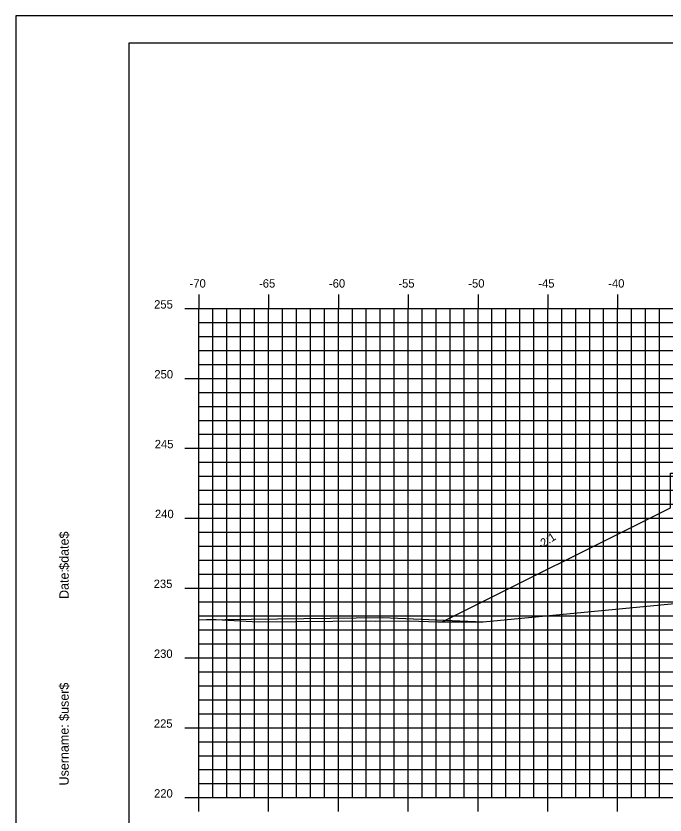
# Model space of a CAD drawing. Extents: x -22 to 1480, y -1511 to 8.
# Drawn here: x 770.3 to 816.8, y -1458.6 to -1401.4 of the extents above; entities that cross this region are included whole.
import ezdxf

# ---------------------------------------------------------------- set-up
doc = ezdxf.new("R2010")
doc.units = 0
for name, color, linetype in [('ANNOTATION', 7, 'Continuous'), ('BORDER', 7, 'Continuous'), ('D_Roadway_Centerline', 7, 'Continuous'), ('H_V ANNOTATION', 7, 'Continuous'), ('MAJOR', 7, 'Continuous'), ('MINOR', 7, 'Continuous'), ('PLOT BOUNDARY', 7, 'Continuous'), ('S_Roadway_Centerline', 7, 'Continuous')]:
    doc.layers.add(name, color=color, linetype=linetype)

msp = doc.modelspace()

# ---------------------------------------------------------------- linework, layer by layer
at = {"layer": 'BORDER'}
for p, q in [((938.426, -1403.331), (778.426, -1403.331)), ((778.426, -1403.331), (778.426, -1508.331))]:
    msp.add_line(p, q, dxfattribs=at)
at = {"layer": 'D_Roadway_Centerline'}
msp.add_lwpolyline([(800.861, -1444.759), (817.217, -1436.581), (817.217, -1434.102), (819.36, -1434.102), (819.36, -1434.602), (832.426, -1428.069), (834.586, -1427.982), (835.426, -1427.949), (837.106, -1427.882), (841.426, -1427.709), (844.786, -1427.642), (853.426, -1427.469), (856.786, -1427.536), (865.426, -1427.709), (868.226, -1427.821), (874.083, -1428.055)], dxfattribs=at)
at = {"layer": 'MAJOR'}
for p, q in [((783.426, -1421.329), (783.426, -1422.331)), ((788.426, -1421.329), (788.426, -1422.331)), ((793.426, -1421.329), (793.426, -1422.331)), ((798.426, -1421.329), (798.426, -1422.331)), ((803.426, -1421.329), (803.426, -1422.331)), ((808.426, -1421.329), (808.426, -1422.331)), ((813.426, -1421.329), (813.426, -1422.331)), ((782.424, -1422.331), (783.426, -1422.331)), ((783.426, -1422.331), (923.426, -1422.331)), ((783.426, -1457.331), (783.426, -1422.331)), ((783.426, -1457.331), (783.426, -1422.331)), ((783.426, -1422.331), (923.426, -1422.331)), ((788.426, -1457.331), (788.426, -1422.331)), ((793.426, -1457.331), (793.426, -1422.331)), ((798.426, -1457.331), (798.426, -1422.331)), ((803.426, -1457.331), (803.426, -1422.331)), ((808.426, -1457.331), (808.426, -1422.331)), ((813.426, -1457.331), (813.426, -1422.331)), ((782.424, -1427.331), (783.426, -1427.331)), ((783.426, -1427.331), (923.426, -1427.331)), ((782.424, -1432.331), (783.426, -1432.331)), ((783.426, -1432.331), (923.426, -1432.331)), ((782.424, -1437.331), (783.426, -1437.331)), ((783.426, -1437.331), (923.426, -1437.331)), ((782.424, -1442.331), (783.426, -1442.331)), ((783.426, -1442.331), (923.426, -1442.331)), ((782.424, -1447.331), (783.426, -1447.331)), ((783.426, -1447.331), (923.426, -1447.331)), ((782.424, -1452.331), (783.426, -1452.331)), ((783.426, -1452.331), (923.426, -1452.331)), ((782.424, -1457.331), (783.426, -1457.331)), ((783.426, -1457.331), (923.426, -1457.331)), ((783.426, -1457.331), (923.426, -1457.331)), ((783.426, -1458.333), (783.426, -1457.331)), ((788.426, -1458.333), (788.426, -1457.331)), ((793.426, -1458.333), (793.426, -1457.331)), ((798.426, -1458.333), (798.426, -1457.331)), ((803.426, -1458.333), (803.426, -1457.331)), ((808.426, -1458.333), (808.426, -1457.331)), ((813.426, -1458.333), (813.426, -1457.331))]:
    msp.add_line(p, q, dxfattribs=at)
at = {"layer": 'MINOR'}
for p, q in [((784.426, -1457.331), (784.426, -1422.331)), ((785.426, -1457.331), (785.426, -1422.331)), ((786.426, -1457.331), (786.426, -1422.331)), ((787.426, -1457.331), (787.426, -1422.331)), ((789.426, -1457.331), (789.426, -1422.331)), ((790.426, -1457.331), (790.426, -1422.331)), ((791.426, -1457.331), (791.426, -1422.331)), ((792.426, -1457.331), (792.426, -1422.331)), ((794.426, -1457.331), (794.426, -1422.331)), ((795.426, -1457.331), (795.426, -1422.331)), ((796.426, -1457.331), (796.426, -1422.331)), ((797.426, -1457.331), (797.426, -1422.331)), ((799.426, -1457.331), (799.426, -1422.331)), ((800.426, -1457.331), (800.426, -1422.331)), ((801.426, -1457.331), (801.426, -1422.331)), ((802.426, -1457.331), (802.426, -1422.331)), ((804.426, -1457.331), (804.426, -1422.331)), ((805.426, -1457.331), (805.426, -1422.331)), ((806.426, -1457.331), (806.426, -1422.331)), ((807.426, -1457.331), (807.426, -1422.331)), ((809.426, -1457.331), (809.426, -1422.331)), ((810.426, -1457.331), (810.426, -1422.331)), ((811.426, -1457.331), (811.426, -1422.331)), ((812.426, -1457.331), (812.426, -1422.331)), ((814.426, -1457.331), (814.426, -1422.331)), ((815.426, -1457.331), (815.426, -1422.331)), ((816.426, -1457.331), (816.426, -1422.331)), ((783.426, -1423.331), (923.426, -1423.331)), ((783.426, -1423.331), (784.428, -1423.331)), ((783.426, -1424.331), (923.426, -1424.331)), ((783.426, -1424.331), (784.428, -1424.331)), ((783.426, -1425.331), (923.426, -1425.331)), ((783.426, -1425.331), (784.428, -1425.331)), ((783.426, -1426.331), (923.426, -1426.331)), ((783.426, -1426.331), (784.428, -1426.331)), ((783.426, -1428.331), (923.426, -1428.331)), ((783.426, -1428.331), (784.428, -1428.331)), ((783.426, -1429.331), (923.426, -1429.331)), ((783.426, -1429.331), (784.428, -1429.331)), ((783.426, -1430.331), (923.426, -1430.331)), ((783.426, -1430.331), (784.428, -1430.331)), ((783.426, -1431.331), (923.426, -1431.331)), ((783.426, -1431.331), (784.428, -1431.331)), ((783.426, -1433.331), (923.426, -1433.331)), ((783.426, -1433.331), (784.428, -1433.331)), ((783.426, -1434.331), (923.426, -1434.331)), ((783.426, -1434.331), (784.428, -1434.331)), ((783.426, -1435.331), (923.426, -1435.331)), ((783.426, -1435.331), (784.428, -1435.331)), ((783.426, -1436.331), (923.426, -1436.331)), ((783.426, -1436.331), (784.428, -1436.331)), ((783.426, -1438.331), (923.426, -1438.331)), ((783.426, -1438.331), (784.428, -1438.331)), ((783.426, -1439.331), (923.426, -1439.331)), ((783.426, -1439.331), (784.428, -1439.331)), ((783.426, -1440.331), (923.426, -1440.331)), ((783.426, -1440.331), (784.428, -1440.331)), ((783.426, -1441.331), (923.426, -1441.331)), ((783.426, -1441.331), (784.428, -1441.331)), ((783.426, -1443.331), (923.426, -1443.331)), ((783.426, -1443.331), (784.428, -1443.331)), ((783.426, -1444.331), (923.426, -1444.331)), ((783.426, -1444.331), (784.428, -1444.331)), ((783.426, -1445.331), (923.426, -1445.331)), ((783.426, -1445.331), (784.428, -1445.331)), ((783.426, -1446.331), (923.426, -1446.331)), ((783.426, -1446.331), (784.428, -1446.331)), ((783.426, -1448.331), (923.426, -1448.331)), ((783.426, -1448.331), (784.428, -1448.331)), ((783.426, -1449.331), (923.426, -1449.331)), ((783.426, -1449.331), (784.428, -1449.331)), ((783.426, -1450.331), (923.426, -1450.331)), ((783.426, -1450.331), (784.428, -1450.331)), ((783.426, -1451.331), (923.426, -1451.331)), ((783.426, -1451.331), (784.428, -1451.331)), ((783.426, -1453.331), (923.426, -1453.331)), ((783.426, -1453.331), (784.428, -1453.331)), ((783.426, -1454.331), (923.426, -1454.331)), ((783.426, -1454.331), (784.428, -1454.331)), ((783.426, -1455.331), (923.426, -1455.331)), ((783.426, -1455.331), (784.428, -1455.331)), ((783.426, -1456.331), (923.426, -1456.331)), ((783.426, -1456.331), (784.428, -1456.331))]:
    msp.add_line(p, q, dxfattribs=at)
at = {"layer": 'PLOT BOUNDARY'}
msp.add_lwpolyline([(770.333, -1511.39), (940.333, -1511.39), (940.333, -1401.39), (770.333, -1401.39)], close=True, dxfattribs=at)
at = {"layer": 'S_Roadway_Centerline'}
for points in [[(783.426, -1444.599), (783.972, -1444.593), (784.661, -1444.585), (787.692, -1444.74), (795.696, -1444.682), (796.068, -1444.697), (798.529, -1444.68), (800.55, -1444.761), (803.789, -1444.743), (821.514, -1443.055)], [(783.426, -1444.599), (796.574, -1444.451), (803.789, -1444.743), (821.514, -1443.055)]]:
    msp.add_lwpolyline(points, dxfattribs=at)

# ---------------------------------------------------------------- texts
at = {"layer": 'ANNOTATION'}
msp.add_text('-2:1', height=0.6, rotation=33.0881, dxfattribs=at).set_placement((807.909, -1439.573))
at = {"layer": 'BORDER'}
for s, p in [('$date$', (774.111, -1441.026)), ('Date:', (774.111, -1443.114)), ('$user$', (774.111, -1451.84)), ('Username:', (774.111, -1456.463))]:
    msp.add_text(s, height=0.6696, rotation=90, dxfattribs=at).set_placement(p)
at = {"layer": 'H_V ANNOTATION'}
for s, p in [('-70', (782.768, -1420.831)), ('-65', (787.744, -1420.831)), ('-60', (792.752, -1420.831)), ('-55', (797.722, -1420.831)), ('-50', (802.73, -1420.831)), ('-45', (807.744, -1420.831)), ('-40', (812.752, -1420.831)), ('255', (780.229, -1422.331)), ('250', (780.245, -1427.331)), ('245', (780.272, -1432.331)), ('240', (780.288, -1437.331)), ('235', (780.197, -1442.331)), ('230', (780.213, -1447.331)), ('225', (780.208, -1452.331)), ('220', (780.224, -1457.331))]:
    msp.add_text(s, height=0.6, dxfattribs=at).set_placement(p)

doc.saveas('drawing.dxf')
